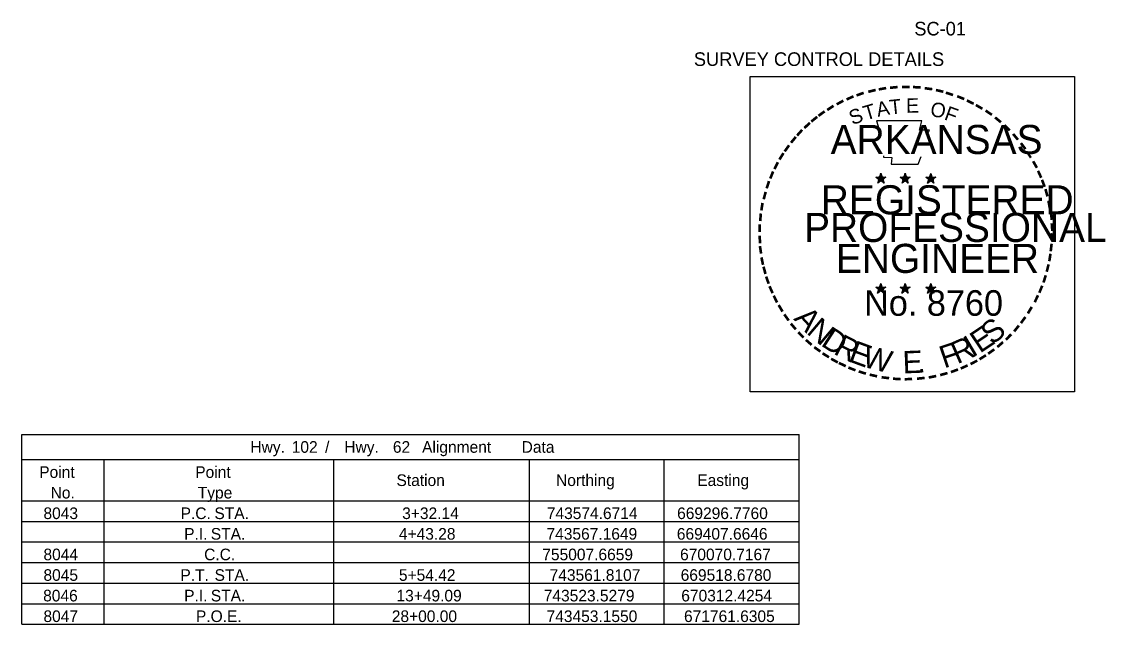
# Model space of a CAD drawing. Extents: x 672566 to 676329, y 739687 to 740710.
# Drawn here: x 674192.9 to 674658.6, y 740423.2 to 740682.3 of the extents above; entities that cross this region are included whole.
import ezdxf

# ---------------------------------------------------------------- set-up
doc = ezdxf.new("R2010")
doc.units = 0
for name, color, linetype in [('R_Border', 7, 'Continuous'), ('R_Border PE', 7, 'Continuous'), ('R_Border Prem', 7, 'Continuous'), ('S_BASELINE', 7, 'Continuous')]:
    doc.layers.add(name, color=color, linetype=linetype)

msp = doc.modelspace()

# ---------------------------------------------------------------- linework, layer by layer
at = {"layer": 'R_Border PE'}
for p, q in [((674559.97, 740615.45), (674562.16, 740614.76)), ((674559.97, 740615.45), (674561.6, 740615.33)), ((674559.97, 740615.45), (674561.6, 740615.2)), ((674559.97, 740615.45), (674561.53, 740615.08)), ((674559.97, 740615.45), (674561.53, 740614.83)), ((674559.97, 740615.45), (674561.47, 740614.7)), ((674559.97, 740615.45), (674561.47, 740614.58)), ((674560.85, 740612.89), (674562.16, 740614.76)), ((674560.85, 740612.89), (674561.53, 740614.64)), ((674562.16, 740617.08), (674561.85, 740615.51)), ((674562.16, 740617.08), (674561.91, 740615.45)), ((674562.16, 740617.08), (674562.1, 740615.51)), ((674562.16, 740614.76), (674562.16, 740617.08)), ((674562.16, 740617.08), (674562.6, 740615.45)), ((674562.16, 740617.08), (674562.47, 740615.51)), ((674562.16, 740617.08), (674562.35, 740615.51)), ((674564.35, 740615.45), (674562.16, 740614.76)), ((674563.53, 740612.89), (674562.16, 740614.76)), ((674564.35, 740615.45), (674562.41, 740615.33)), ((674564.35, 740615.45), (674562.53, 740615.14)), ((674564.35, 740615.45), (674562.53, 740615.01)), ((674563.53, 740612.89), (674562.66, 740614.7)), ((674563.53, 740612.89), (674562.78, 740614.76)), ((674564.35, 740615.45), (674562.97, 740614.89)), ((674564.35, 740615.45), (674563.1, 740614.83)), ((674564.35, 740615.45), (674563.16, 740614.76)), ((674570.41, 740615.45), (674572.6, 740614.76)), ((674570.41, 740615.45), (674572.03, 740615.33)), ((674570.41, 740615.45), (674572.03, 740615.2)), ((674570.41, 740615.45), (674571.97, 740615.08)), ((674570.41, 740615.45), (674571.91, 740614.83)), ((674570.41, 740615.45), (674571.91, 740614.7)), ((674570.41, 740615.45), (674571.91, 740614.58)), ((674571.28, 740612.89), (674572.6, 740614.76)), ((674571.28, 740612.89), (674571.97, 740614.64)), ((674572.6, 740617.08), (674572.28, 740615.51)), ((674572.6, 740617.08), (674572.35, 740615.45)), ((674572.6, 740617.08), (674572.47, 740615.51)), ((674572.6, 740614.76), (674572.6, 740617.08)), ((674572.6, 740617.08), (674573.03, 740615.45)), ((674572.6, 740617.08), (674572.91, 740615.51)), ((674572.6, 740617.08), (674572.72, 740615.51)), ((674574.78, 740615.45), (674572.6, 740614.76)), ((674573.97, 740612.89), (674572.6, 740614.76)), ((674574.78, 740615.45), (674572.85, 740615.33)), ((674574.78, 740615.45), (674572.97, 740615.14)), ((674574.78, 740615.45), (674572.97, 740615.01)), ((674573.97, 740612.89), (674573.1, 740614.7)), ((674573.97, 740612.89), (674573.22, 740614.76)), ((674574.78, 740615.45), (674573.41, 740614.89)), ((674574.78, 740615.45), (674573.53, 740614.83)), ((674574.78, 740615.45), (674573.6, 740614.76)), ((674581.47, 740615.39), (674583.66, 740614.7)), ((674581.47, 740615.39), (674583.1, 740615.2)), ((674581.47, 740615.39), (674583.03, 740615.08)), ((674581.47, 740615.39), (674583.03, 740615.01)), ((674581.47, 740615.39), (674582.97, 740614.76)), ((674581.47, 740615.39), (674582.97, 740614.64)), ((674581.47, 740615.39), (674582.97, 740614.51)), ((674582.28, 740612.83), (674583.66, 740614.7)), ((674583.66, 740616.95), (674583.28, 740615.45)), ((674583.66, 740616.95), (674583.41, 740615.39)), ((674583.66, 740616.95), (674583.53, 740615.39)), ((674583.66, 740614.7), (674583.66, 740616.95)), ((674583.66, 740616.95), (674584.1, 740615.39)), ((674583.66, 740616.95), (674583.97, 740615.39)), ((674583.66, 740616.95), (674583.78, 740615.45)), ((674585.85, 740615.39), (674583.66, 740614.7)), ((674584.97, 740612.83), (674583.66, 740614.7)), ((674585.85, 740615.39), (674583.91, 740615.26)), ((674585.85, 740615.39), (674584.03, 740615.08)), ((674585.85, 740615.39), (674584.03, 740614.95)), ((674584.97, 740612.83), (674584.16, 740614.64)), ((674584.97, 740612.83), (674584.28, 740614.64)), ((674585.85, 740615.39), (674584.47, 740614.83)), ((674585.85, 740615.39), (674584.53, 740614.76)), ((674585.85, 740615.39), (674584.66, 740614.7)), ((674560.85, 740612.89), (674561.6, 740614.45)), ((674560.85, 740612.89), (674561.72, 740614.39)), ((674560.85, 740612.89), (674562.16, 740614.26)), ((674560.85, 740612.89), (674561.91, 740614.2)), ((674560.85, 740612.89), (674562.22, 740614.08)), ((674563.53, 740612.89), (674562.16, 740614.26)), ((674563.53, 740612.89), (674562.16, 740614.08)), ((674563.53, 740612.89), (674562.41, 740614.2)), ((674563.53, 740612.89), (674562.6, 740614.45)), ((674571.28, 740612.89), (674572.03, 740614.45)), ((674571.28, 740612.89), (674572.16, 740614.39)), ((674571.28, 740612.89), (674572.6, 740614.26)), ((674571.28, 740612.89), (674572.35, 740614.2)), ((674571.28, 740612.89), (674572.66, 740614.08)), ((674573.97, 740612.89), (674572.6, 740614.26)), ((674573.97, 740612.89), (674572.6, 740614.08)), ((674573.97, 740612.89), (674572.85, 740614.2)), ((674573.97, 740612.89), (674573.03, 740614.45)), ((674582.28, 740612.83), (674583.03, 740614.58)), ((674582.28, 740612.83), (674583.1, 740614.39)), ((674582.28, 740612.83), (674583.22, 740614.33)), ((674582.28, 740612.83), (674583.66, 740614.2)), ((674582.28, 740612.83), (674583.41, 740614.14)), ((674582.28, 740612.83), (674583.72, 740614.01)), ((674584.97, 740612.83), (674583.66, 740614.2)), ((674584.97, 740612.83), (674583.66, 740614.01)), ((674584.97, 740612.83), (674583.91, 740614.14)), ((674584.97, 740612.83), (674584.1, 740614.39)), ((674559.97, 740568.14), (674562.16, 740567.45)), ((674559.97, 740568.14), (674561.6, 740567.95)), ((674559.97, 740568.14), (674561.53, 740567.83)), ((674559.97, 740568.14), (674561.53, 740567.76)), ((674559.97, 740568.14), (674561.47, 740567.51)), ((674559.97, 740568.14), (674561.47, 740567.39)), ((674559.97, 740568.14), (674561.47, 740567.26)), ((674562.16, 740569.7), (674561.78, 740568.2)), ((674562.16, 740569.7), (674561.91, 740568.14)), ((674562.16, 740569.7), (674562.03, 740568.14)), ((674562.16, 740567.45), (674562.16, 740569.7)), ((674562.16, 740569.7), (674562.6, 740568.14)), ((674562.16, 740569.7), (674562.47, 740568.14)), ((674562.16, 740569.7), (674562.28, 740568.14)), ((674564.35, 740568.14), (674562.16, 740567.45)), ((674564.35, 740568.14), (674562.41, 740568.01)), ((674564.35, 740568.14), (674562.53, 740567.83)), ((674564.35, 740568.14), (674562.53, 740567.7)), ((674564.35, 740568.14), (674562.91, 740567.58)), ((674564.35, 740568.14), (674563.03, 740567.51)), ((674564.35, 740568.14), (674563.16, 740567.39)), ((674570.41, 740568.14), (674572.6, 740567.45)), ((674570.41, 740568.14), (674571.97, 740567.95)), ((674570.41, 740568.14), (674571.97, 740567.83)), ((674570.41, 740568.14), (674571.97, 740567.76)), ((674570.41, 740568.14), (674571.91, 740567.51)), ((674570.41, 740568.14), (674571.91, 740567.39)), ((674570.41, 740568.14), (674571.91, 740567.26)), ((674572.6, 740569.7), (674572.22, 740568.2)), ((674572.6, 740569.7), (674572.35, 740568.14)), ((674572.6, 740569.7), (674572.47, 740568.14)), ((674572.6, 740567.45), (674572.6, 740569.7)), ((674572.6, 740569.7), (674572.97, 740568.14)), ((674572.6, 740569.7), (674572.91, 740568.14)), ((674572.6, 740569.7), (674572.72, 740568.14)), ((674574.72, 740568.14), (674572.6, 740567.45)), ((674574.72, 740568.14), (674572.85, 740568.01)), ((674574.72, 740568.14), (674572.97, 740567.83)), ((674574.72, 740568.14), (674572.97, 740567.7)), ((674574.72, 740568.14), (674573.35, 740567.58)), ((674574.72, 740568.14), (674573.47, 740567.51)), ((674574.72, 740568.14), (674573.6, 740567.39)), ((674581.47, 740568.08), (674583.66, 740567.39)), ((674581.47, 740568.08), (674583.03, 740567.89)), ((674581.47, 740568.08), (674583.03, 740567.76)), ((674581.47, 740568.08), (674582.97, 740567.64)), ((674581.47, 740568.08), (674582.97, 740567.45)), ((674581.47, 740568.08), (674582.91, 740567.26)), ((674581.47, 740568.08), (674582.91, 740567.14)), ((674583.66, 740569.64), (674583.28, 740568.08)), ((674583.66, 740569.64), (674583.41, 740568.08)), ((674583.66, 740569.64), (674583.53, 740568.08)), ((674583.66, 740567.39), (674583.66, 740569.64)), ((674583.66, 740569.64), (674584.03, 740568.08)), ((674583.66, 740569.64), (674583.97, 740568.08)), ((674583.66, 740569.64), (674583.78, 740568.08)), ((674585.78, 740568.08), (674583.66, 740567.39)), ((674585.78, 740568.08), (674583.91, 740567.95)), ((674585.78, 740568.08), (674584.03, 740567.76)), ((674585.78, 740568.08), (674584.03, 740567.64)), ((674585.78, 740568.08), (674584.41, 740567.51)), ((674585.78, 740568.08), (674584.53, 740567.39)), ((674585.78, 740568.08), (674584.6, 740567.33)), ((674560.78, 740565.58), (674562.16, 740567.45)), ((674560.78, 740565.58), (674561.53, 740567.33)), ((674560.78, 740565.58), (674561.6, 740567.08)), ((674560.78, 740565.58), (674561.72, 740567.01)), ((674560.78, 740565.58), (674562.16, 740566.95)), ((674560.78, 740565.58), (674561.91, 740566.89)), ((674560.78, 740565.58), (674562.16, 740566.76)), ((674563.47, 740565.58), (674562.1, 740566.76)), ((674563.47, 740565.58), (674562.16, 740567.45)), ((674563.47, 740565.58), (674562.16, 740566.89)), ((674563.47, 740565.58), (674562.35, 740566.89)), ((674563.47, 740565.58), (674562.6, 740567.39)), ((674563.47, 740565.58), (674562.6, 740567.14)), ((674563.47, 740565.58), (674562.78, 740567.39)), ((674571.22, 740565.58), (674572.6, 740567.45)), ((674571.22, 740565.58), (674571.97, 740567.33)), ((674571.22, 740565.58), (674572.03, 740567.08)), ((674571.22, 740565.58), (674572.16, 740567.01)), ((674571.22, 740565.58), (674572.6, 740566.95)), ((674571.22, 740565.58), (674572.35, 740566.89)), ((674571.22, 740565.58), (674572.6, 740566.76)), ((674573.91, 740565.58), (674572.53, 740566.76)), ((674573.91, 740565.58), (674572.6, 740567.45)), ((674573.91, 740565.58), (674572.6, 740566.89)), ((674573.91, 740565.58), (674572.78, 740566.89)), ((674573.91, 740565.58), (674573.03, 740567.39)), ((674573.91, 740565.58), (674573.03, 740567.14)), ((674573.91, 740565.58), (674573.22, 740567.39)), ((674582.28, 740565.51), (674583.66, 740567.39)), ((674582.28, 740565.51), (674582.97, 740567.26)), ((674582.28, 740565.51), (674583.03, 740567.01)), ((674582.28, 740565.51), (674583.22, 740566.95)), ((674582.28, 740565.51), (674583.41, 740566.83)), ((674582.28, 740565.51), (674583.6, 740566.83)), ((674582.28, 740565.51), (674583.66, 740566.7)), ((674584.97, 740565.51), (674583.6, 740566.83)), ((674584.97, 740565.51), (674583.6, 740566.64)), ((674584.97, 740565.51), (674583.66, 740567.39)), ((674584.97, 740565.51), (674583.85, 740566.83)), ((674584.97, 740565.51), (674584.03, 740567.01)), ((674584.97, 740565.51), (674584.1, 740567.33)), ((674584.97, 740565.51), (674584.22, 740567.33))]:
    msp.add_line(p, q, dxfattribs=at)
for points in [[(674560.28, 740639.7), (674561.91, 740634.51)], [(674582.22, 740633.95), (674583.1, 740635.7), (674578.78, 740635.58), (674579.72, 740639.7), (674560.28, 740639.7)], [(674563.35, 740624.58), (674563.35, 740624.01), (674566.85, 740623.89), (674566.53, 740620.95), (674578.22, 740620.95), (674579.47, 740624.26)], [(674562.16, 740617.08), (674563.53, 740612.89), (674559.97, 740615.45), (674564.35, 740615.45), (674560.85, 740612.89), (674562.16, 740617.08)], [(674572.6, 740617.08), (674573.97, 740612.89), (674570.41, 740615.45), (674574.78, 740615.45), (674571.28, 740612.89), (674572.6, 740617.08)], [(674583.66, 740616.95), (674584.97, 740612.83), (674581.47, 740615.39), (674585.85, 740615.39), (674582.28, 740612.83), (674583.66, 740616.95)], [(674562.16, 740569.7), (674563.47, 740565.58), (674559.97, 740568.14), (674564.35, 740568.14), (674560.78, 740565.58), (674562.16, 740569.7)], [(674572.6, 740569.7), (674573.91, 740565.58), (674570.41, 740568.14), (674574.72, 740568.14), (674571.22, 740565.58), (674572.6, 740569.7)], [(674583.66, 740569.64), (674584.97, 740565.51), (674581.47, 740568.08), (674585.78, 740568.08), (674582.28, 740565.51), (674583.66, 740569.64)]]:
    msp.add_lwpolyline(points, dxfattribs=at)
for centre, radius in [((674562.18, 740614.76), 1.08), ((674562.18, 740614.76), 0.975), ((674562.18, 740614.76), 0.904), ((674562.18, 740614.76), 0.83), ((674562.18, 740614.76), 0.723), ((674562.18, 740614.76), 0.672), ((674562.18, 740614.76), 0.619), ((674562.18, 740614.76), 0.533), ((674562.18, 740614.76), 0.467), ((674562.18, 740614.76), 0.388), ((674562.18, 740614.76), 0.31), ((674562.18, 740614.76), 0.231), ((674562.18, 740614.76), 0.185), ((674562.18, 740614.76), 0.0901), ((674572.61, 740614.76), 1.08), ((674572.61, 740614.76), 0.975), ((674572.61, 740614.76), 0.904), ((674572.61, 740614.76), 0.83), ((674572.61, 740614.76), 0.723), ((674572.61, 740614.76), 0.672), ((674572.61, 740614.76), 0.619), ((674572.61, 740614.76), 0.533), ((674572.61, 740614.76), 0.467), ((674572.61, 740614.76), 0.388), ((674572.61, 740614.76), 0.31), ((674572.61, 740614.76), 0.231), ((674572.61, 740614.76), 0.185), ((674572.61, 740614.76), 0.0901), ((674583.65, 740614.68), 1.08), ((674583.65, 740614.68), 0.975), ((674583.65, 740614.68), 0.904), ((674583.65, 740614.68), 0.83), ((674583.65, 740614.68), 0.723), ((674583.65, 740614.68), 0.672), ((674583.65, 740614.68), 0.619), ((674583.65, 740614.68), 0.533), ((674583.65, 740614.68), 0.467), ((674583.65, 740614.68), 0.388), ((674583.65, 740614.68), 0.31), ((674583.65, 740614.68), 0.231), ((674583.65, 740614.68), 0.185), ((674583.65, 740614.68), 0.0901), ((674562.15, 740567.43), 1.08), ((674562.15, 740567.43), 0.975), ((674562.15, 740567.43), 0.904), ((674562.15, 740567.43), 0.83), ((674562.15, 740567.43), 0.723), ((674562.15, 740567.43), 0.672), ((674562.15, 740567.43), 0.619), ((674572.58, 740567.43), 1.08), ((674572.58, 740567.43), 0.975), ((674572.58, 740567.43), 0.904), ((674572.58, 740567.43), 0.83), ((674572.58, 740567.43), 0.723), ((674572.58, 740567.43), 0.672), ((674572.58, 740567.43), 0.619), ((674583.63, 740567.35), 1.08), ((674583.63, 740567.35), 0.975), ((674583.63, 740567.35), 0.904), ((674583.63, 740567.35), 0.83), ((674583.63, 740567.35), 0.723), ((674562.15, 740567.43), 0.533), ((674562.15, 740567.43), 0.467), ((674562.15, 740567.43), 0.388), ((674562.15, 740567.43), 0.31), ((674562.15, 740567.43), 0.231), ((674562.15, 740567.43), 0.185), ((674562.15, 740567.43), 0.0901), ((674572.58, 740567.43), 0.533), ((674572.58, 740567.43), 0.467), ((674572.58, 740567.43), 0.388), ((674572.58, 740567.43), 0.31), ((674572.58, 740567.43), 0.231), ((674572.58, 740567.43), 0.185), ((674572.58, 740567.43), 0.0901), ((674583.63, 740567.35), 0.672), ((674583.63, 740567.35), 0.619), ((674583.63, 740567.35), 0.533), ((674583.63, 740567.35), 0.467), ((674583.63, 740567.35), 0.388), ((674583.63, 740567.35), 0.31), ((674583.63, 740567.35), 0.231), ((674583.63, 740567.35), 0.185), ((674583.63, 740567.35), 0.0901)]:
    msp.add_circle(centre, radius, dxfattribs=at)
at = {"layer": 'R_Border Prem'}
msp.add_lwpolyline([(674505.94, 740658.75), (674645.44, 740658.75), (674645.44, 740523.12), (674505.94, 740523.12)], close=True, dxfattribs=at)
at = {"layer": 'S_BASELINE'}
for p, q in [((674192.88, 740504.83), (674527.08, 740504.83)), ((674192.88, 740423.16), (674192.88, 740504.83)), ((674527.08, 740423.16), (674527.08, 740504.83)), ((674192.88, 740493.98), (674527.08, 740493.98)), ((674228.29, 740423.16), (674228.29, 740493.98)), ((674327, 740423.16), (674327, 740493.98)), ((674411.1, 740423.16), (674411.1, 740493.98)), ((674469.09, 740423.16), (674469.09, 740493.98)), ((674192.88, 740476.27), (674527.08, 740476.27)), ((674192.88, 740476.27), (674228.29, 740476.27)), ((674192.88, 740467.42), (674527.08, 740467.42)), ((674192.88, 740458.57), (674527.08, 740458.57)), ((674192.88, 740449.72), (674527.08, 740449.72)), ((674192.88, 740440.86), (674527.08, 740440.86)), ((674192.88, 740432.01), (674527.08, 740432.01)), ((674192.88, 740423.16), (674527.08, 740423.16))]:
    msp.add_line(p, q, dxfattribs=at)

# ---------------------------------------------------------------- texts
at = {"layer": 'R_Border'}
for s, height, p in [('SC-01', 5.861, (674576.54, 740676.35)), ('SURVEY CONTROL DETAILS', 5.862, (674481.79, 740663.25))]:
    msp.add_text(s, height=height, rotation=360, dxfattribs=at).set_placement(p)
at = {"layer": 'R_Border PE'}
for s, height, rotation, p in [('-', 10, 19.1761, (674552.41, 740646.76)), ('-', 10, 13.6301, (674557.1, 740648.26)), ('-', 10, 10.2193, (674561.35, 740649.26)), ('-', 10, 5.8968, (674565.91, 740649.95)), ('-', 10, 0.1862, (674570.72, 740650.39)), ('-', 10, 357.743, (674575.28, 740650.33)), ('-', 10, 352.1617, (674579.91, 740649.95)), ('-', 10, 347.2049, (674584.41, 740649.26)), ('-', 10, 342.3362, (674588.35, 740648.26)), ('-', 10, 28.7918, (674544.53, 740643.08)), ('-', 10, 24.3072, (674548.47, 740645.08)), ('A', 6.25, 11.2132, (674560.85, 740641.33)), ('T', 6.25, 6.0228, (674566.16, 740642.39)), ('E', 6.25, 0.8323, (674573.03, 740643.08)), ('O', 6.25, 350.4515, (674583.1, 740641.76)), ('-', 10, 337.8551, (674592.97, 740646.89)), ('-', 10, 334.1211, (674596.91, 740645.2)), ('-', 10, 36.2317, (674537.16, 740638.33)), ('-', 10, 34.0636, (674540.78, 740640.76)), ('S', 6.25, 21.594, (674549.97, 740637.7)), ('T', 6.25, 16.4036, (674555.66, 740639.76)), ('F', 6.25, 340.0707, (674589.03, 740640.33)), ('-', 10, 329.6409, (674600.53, 740643.45)), ('-', 10, 325.8627, (674604.53, 740641.2)), ('-', 10, 42.9622, (674531.47, 740633.33)), ('-', 10, 38.9507, (674534.22, 740635.95)), ('ARKANSAS', 12.5, 360, (674540.6, 740625.39)), ('-', 10, 320.5297, (674608.35, 740638.51)), ('-', 10, 315.5786, (674612.1, 740635.45)), ('-', 10, 48.423, (674528.66, 740630.33)), ('-', 10, 309.8797, (674615.66, 740632.01)), ('-', 10, 54.2325, (674523.6, 740623.76)), ('-', 10, 50.6142, (674526.16, 740627.33)), ('-', 10, 306.6522, (674618.91, 740628.26)), ('-', 10, 58.0706, (674521.53, 740620.45)), ('-', 8.75, 303.6753, (674621.97, 740624.7)), ('-', 10, 62.8713, (674519.6, 740616.64)), ('-', 10, 299.6684, (674623.97, 740620.89)), ('-', 10, 67.7743, (674517.97, 740612.83)), ('-', 10, 294.6628, (674625.97, 740617.08)), ('-', 10, 72.3945, (674516.6, 740608.89)), ('REGISTERED', 12.5, 360, (674536.35, 740599.45)), ('-', 10, 290.5728, (674627.6, 740613.51)), ('-', 10, 285.1233, (674629.03, 740609.89)), ('-', 10, 75.461, (674515.41, 740604.39)), ('-', 10, 280.5493, (674630.28, 740605.2)), ('-', 10, 81.2013, (674514.53, 740599.95)), ('-', 10, 85.1863, (674514.1, 740595.64)), ('PROFESSIONAL', 12.4999, 360, (674529.16, 740587.58)), ('-', 10, 276.5962, (674631.35, 740600.45)), ('-', 10, 89.0622, (674513.91, 740591.26)), ('-', 10, 274.3301, (674631.72, 740595.89)), ('-', 10, 269.9407, (674631.91, 740591.95)), ('-', 10, 94.1959, (674514.16, 740586.7)), ('ENGINEER', 12.5, 360, (674542.85, 740574.26)), ('-', 10, 263.5172, (674631.78, 740587.83)), ('-', 10, 98.9479, (674514.6, 740582.58)), ('-', 10, 260.9953, (674631.35, 740583.7)), ('-', 10, 101.7149, (674515.41, 740577.95)), ('-', 10, 255.7626, (674630.66, 740579.45)), ('-', 10, 105.4578, (674516.47, 740574.26)), ('-', 10, 109.0874, (674517.78, 740570.33)), ('-', 10, 252.8681, (674629.53, 740574.95)), ('-', 10, 114.0643, (674519.41, 740566.58)), ('-', 10, 247.8887, (674628.16, 740570.76)), ('-', 10, 115.7288, (674521.28, 740562.7)), ('No. 8760', 11, 360, (674554.96, 740555.83)), ('-', 10, 244.6197, (674626.47, 740566.83)), ('-', 10, 120.4471, (674523.53, 740559.08)), ('-', 10, 239.0712, (674624.03, 740562.14)), ('-', 10, 125.8934, (674526.03, 740555.58)), ('A', 9.62, 312.4727, (674524.41, 740554.38)), ('N', 9.62, 319.8362, (674529.84, 740548.45)), ('S', 9.62, 39.723, (674610.07, 740542.98)), ('-', 10, 233.8452, (674621.53, 740558.08)), ('-', 10, 130.7181, (674528.91, 740552.08)), ('D', 9.62, 327.1996, (674535.99, 740543.26)), ('E', 9.62, 33.8878, (674604.73, 740539.5)), ('-', 10, 231.2538, (674618.85, 740554.51)), ('-', 10, 134.2238, (674532.16, 740548.7)), ('-', 10, 138.9338, (674535.41, 740545.83)), ('R', 9.62, 333.1738, (674541.43, 740539.66)), ('E', 9.62, 339.7037, (674547.77, 740536.4)), ('R', 9.62, 24.0235, (674595, 740534.9)), ('I', 9.62, 30.5534, (674601.53, 740537.76)), ('-', 10, 221.0851, (674612.6, 740547.83)), ('-', 10, 225.7653, (674615.85, 740551.01)), ('-', 10, 144.6463, (674538.91, 740543.26)), ('-', 10, 148.0898, (674542.41, 740540.95)), ('W', 9.62, 345.5389, (674553.72, 740534.11)), ('E', 9.62, 2.2804, (674571.69, 740531.01)), ('F', 9.62, 18.6051, (674589.35, 740533.11)), ('-', 10, 215.7363, (674609.16, 740544.89)), ('-', 10, 151.5704, (674546.03, 740538.89)), ('-', 10, 154.6002, (674549.28, 740537.39)), ('-', 10, 207.3568, (674602.35, 740540.26)), ('-', 10, 212.2491, (674605.78, 740542.45)), ('-', 10, 158.5612, (674553.22, 740535.76)), ('-', 10, 162.7983, (674557.47, 740534.45)), ('-', 10, 167.5555, (674561.97, 740533.45)), ('.', 9.62, 8.1156, (674578.07, 740531.18)), ('-', 10, 195.4743, (674590.35, 740535.08)), ('-', 10, 200.7184, (674594.53, 740536.58)), ('-', 10, 204.2516, (674598.41, 740538.26)), ('-', 10, 173.1155, (674566.78, 740532.76)), ('-', 10, 176.5183, (674571.47, 740532.39)), ('-', 10, 181.5918, (674576.1, 740532.51)), ('-', 10, 185.8167, (674581.16, 740533.01)), ('-', 10, 191.2858, (674585.78, 740533.83))]:
    msp.add_text(s, height=height, rotation=rotation, dxfattribs=at).set_placement(p)
at = {"layer": 'S_BASELINE'}
for s, p in [('Hwy.', (674291.2, 740496.93)), (' 102', (674307.09, 740496.93)), (' /', (674321.44, 740496.93)), (' Hwy.', (674329.7, 740496.93)), (' 62', (674350.58, 740496.93)), (' Alignment', (674363.12, 740496.93)), (' Data', (674405.9, 740496.93)), ('Point', (674200.42, 740486.13)), ('Point', (674267.48, 740486.13)), ('Station', (674353.97, 740482.63)), ('Northing', (674422.56, 740482.63)), ('Easting', (674483.26, 740482.63)), ('No.', (674205.31, 740477.27)), ('Type', (674268.56, 740477.27)), ('8043', (674202.24, 740468.42)), ('P.C.', (674261.19, 740468.42)), (' STA.', (674273.85, 740468.42)), ('3+32.14', (674356.43, 740468.42)), ('743574.6714', (674418.59, 740468.42)), ('669296.7760', (674474.59, 740468.42)), ('P.I.', (674262.72, 740459.57)), (' STA.', (674272.31, 740459.57)), ('4+43.28', (674355.01, 740459.57)), ('743567.1649', (674418.45, 740459.57)), ('669407.6646', (674474.47, 740459.57)), ('8044', (674202.24, 740450.71)), ('C.C.', (674271.31, 740450.71)), ('755007.6659', (674416.64, 740450.71)), ('670070.7167', (674475.86, 740450.71)), ('8045', (674202.24, 740441.86)), (' STA.', (674273.93, 740441.86)), ('5+54.42', (674355.01, 740441.86)), ('743561.8107', (674419.8, 740441.86)), ('669518.6780', (674476.12, 740441.86)), ('P.T.', (674261.11, 740441.86)), ('8046', (674202.11, 740433.01)), ('P.I.', (674262.72, 740433.01)), (' STA.', (674272.31, 740433.01)), ('13+49.09', (674353.97, 740433.01)), ('743523.5279', (674417.27, 740433.01)), ('670312.4254', (674476.38, 740433.01)), ('8047', (674202.24, 740424.15)), ('P.O.E.', (674267.77, 740424.15)), ('28+00.00', (674351.96, 740424.15)), ('743453.1550', (674418.49, 740424.15)), ('671761.6305', (674477.56, 740424.15))]:
    msp.add_text(s, height=4.994, dxfattribs=at).set_placement(p)

doc.saveas('drawing.dxf')
